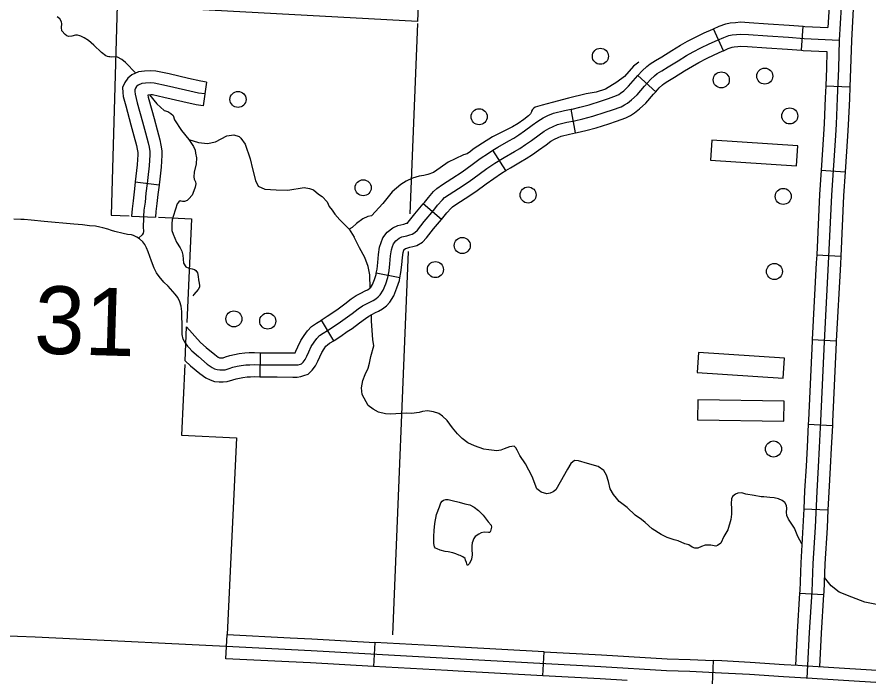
# Model space of a CAD drawing. Extents: x 653372 to 905732, y 627442 to 787275.
# Drawn here: x 693311 to 698620, y 773781 to 777895 of the extents above; entities that cross this region are included whole.
import ezdxf

# ---------------------------------------------------------------- set-up
doc = ezdxf.new("R2010")
doc.units = 0
for name, color, linetype in [('31', 7, 'Continuous'), ('32', 7, 'Continuous'), ('33', 7, 'Continuous'), ('34', 7, 'Continuous'), ('35', 7, 'Continuous'), ('45', 7, 'Continuous'), ('5', 7, 'Continuous'), ('56', 7, 'Continuous'), ('57', 7, 'Continuous'), ('6', 7, 'Continuous')]:
    doc.layers.add(name, color=color, linetype=linetype)

msp = doc.modelspace()

# ---------------------------------------------------------------- linework, layer by layer
at = {"layer": '31'}
for p, q in [((695541.1, 773996.8), (695532.7, 773847.1)), ((696587.2, 773789.1), (696595.4, 773938.9)), ((697649.5, 773883.7), (697642.2, 773733.9))]:
    msp.add_line(p, q, dxfattribs=at)
for points in [[(694613.2, 773895.4), (694620.3, 774045.3), (695013.4, 774025.5)], [(695013.4, 774025.5), (695147.9, 774018.7), (695541.1, 773996.8)], [(701014, 773626.2), (700871.6, 773634.1), (700687.4, 773643.3), (700148.3, 773669.2), (699281.3, 773712.3), (698930.8, 773730.2), (698462, 773758.9), (698233.7, 773773.6), (698228.6, 773773.8), (698087.3, 773782.3), (697875.7, 773796), (697700.5, 773806.1), (697503.3, 773815.7), (697359.2, 773820), (696949.2, 773844.5), (695998.5, 773896.2), (695143.9, 773943.8), (694614.2, 773970.5)], [(696068.2, 773967.6), (696002.6, 773971.1), (695541.1, 773996.8)], [(696595.4, 773938.9), (696068.2, 773967.6)], [(696595.4, 773938.9), (696953.5, 773919.4), (697122.9, 773909.3)], [(697122.9, 773909.3), (697362.6, 773895), (697506.2, 773890.6), (697649.5, 773883.7)], [(695005.9, 773875.7), (694613.2, 773895.4)], [(695532.7, 773847.1), (695139.9, 773869), (695005.9, 773875.7)], [(696060, 773817.8), (695994.4, 773821.4), (695532.7, 773847.1)], [(698177.4, 773852), (698092, 773857.2), (697880.3, 773870.8), (697704.4, 773881), (697649.5, 773883.7)], [(698704.4, 773819.2), (698466.8, 773833.7), (698237.3, 773848.6), (698232, 773848.7), (698177.4, 773852)], [(696587.2, 773789.1), (696060, 773817.8)], [(697114, 773759.5), (696944.9, 773769.6), (696587.2, 773789.1)]]:
    msp.add_lwpolyline(points, dxfattribs=at)
at = {"layer": '32'}
for p, q in [((698199.1, 777688.4), (698209.7, 777838)), ((697714.8, 777685.6), (697651.7, 777821.7)), ((697291.5, 777430.1), (697179.8, 777530.2)), ((698351, 777466.3), (698500.9, 777460.5)), ((696792.4, 777173.4), (696764.1, 777320.7)), ((696357.2, 776938.1), (696277, 777064.9)), ((698322.4, 776941.2), (698472, 776931.2)), ((695957.2, 776634.2), (695843, 776731.4)), ((698294.4, 776412.5), (698444.3, 776405.4)), ((695697.5, 776269.2), (695550.3, 776297.9)), ((695284.9, 775877.4), (695207.7, 776006)), ((694358, 775752.1), (694367.9, 775964.5)), ((698266.5, 775885.7), (698416.3, 775877.7)), ((694825.9, 775653), (694828, 775803)), ((698242.4, 775358.4), (698392.2, 775350.1)), ((698214.3, 774830.5), (698364.2, 774823.5)), ((698187.8, 774304.3), (698337.6, 774295.2))]:
    msp.add_line(p, q, dxfattribs=at)
for points in [[(698493.8, 779045.9), (698478.6, 778678.4), (698468.5, 778464.1), (698452.9, 778065.9), (698435.6, 777752.1), (698430.3, 777575.1), (698423.1, 777389.1), (698416.7, 777228.1), (698412, 777157.9), (698387.1, 776784.8), (698367, 776358.7), (698340.8, 775870.7), (698318.6, 775377.8), (698309.4, 775211), (698303.2, 775092), (698294.4, 774937.5), (698284, 774714.5), (698271, 774489.6), (698263.6, 774314.8), (698248, 774058.3), (698237.7, 773854.9), (698233.7, 773773.6)], [(698373.9, 777995), (698364.8, 777830.5)], [(698523.6, 777986.7), (698510.5, 777748.9), (698505.2, 777572.5), (698500.9, 777460.5)], [(697651.7, 777821.7), (697687.1, 777838), (697727.3, 777852.2), (697756.1, 777858.4), (697787.6, 777862.1), (697820.3, 777864.7), (697874.1, 777861.2), (697992.6, 777853.1), (698123.7, 777844.1), (698209.7, 777838)], [(698209.7, 777838), (698220, 777837.3), (698364.8, 777830.5)], [(695513.3, 776120.9), (695529.8, 776128.2), (695547.5, 776138.9), (695562.3, 776150.2), (695573.4, 776163.1), (695592.3, 776192.3), (695608.6, 776232.3), (695621.6, 776271.9), (695629.6, 776312.7), (695633.8, 776357.6), (695637.9, 776406.2), (695644.1, 776444.2), (695650.4, 776466), (695657, 776482.1), (695671.1, 776500.2), (695692.5, 776516.7), (695710.2, 776524.6), (695740.6, 776532.4), (695758.8, 776537.5), (695773.5, 776541.6), (695791.2, 776551.7), (695806.3, 776567.6), (695847.9, 776621.4), (695907.7, 776691.8), (695932.3, 776722.6), (695961.9, 776756), (695975.8, 776769.6), (696004, 776789.6), (696062.5, 776826.6), (696127.8, 776869.7), (696191.6, 776916.1), (696239.9, 776951.2), (696289.6, 776984.1), (696347.1, 777020.5), (696412.1, 777058), (696445.5, 777076.6), (696480.8, 777100.3), (696517, 777125.6), (696564.7, 777160.2), (696596.9, 777183.9), (696625.6, 777200.1), (696651.3, 777213.4), (696678.5, 777224.8), (696738, 777239.3), (696786.1, 777248.6), (696837.6, 777260), (696898.8, 777277.2), (696976, 777301.4), (697022.6, 777317.4), (697076.6, 777336.6), (697097.7, 777347.2), (697116.1, 777359), (697140.8, 777379.1), (697176.1, 777411.2), (697221.6, 777464.4), (697259.4, 777506.6), (697284.2, 777529.4), (697300.9, 777543), (697329, 777560.2), (697369.1, 777584.3), (697431, 777622.9), (697482.5, 777655.1), (697525.4, 777678), (697573.4, 777703.5), (697623.6, 777729), (697676.6, 777750.5), (697715.3, 777768.5), (697747.7, 777779.9), (697768.4, 777784.3), (697794.9, 777787.4), (697820.8, 777789.5), (697869.1, 777786.3), (697987.5, 777778.3), (698118.5, 777769.3), (698215.6, 777762.4), (698435.6, 777752.1)], [(697179.8, 777530.2), (697205.9, 777559.3), (697235.2, 777586.2), (697257.6, 777604.4), (697290.1, 777624.3), (697329.9, 777648.2), (697391.2, 777686.5), (697445, 777720.1), (697490.1, 777744.2), (697538.8, 777770.1), (697592.5, 777797.4), (697646.7, 777819.3), (697651.8, 777821.7)], [(697291.5, 777430.1), (697312.8, 777453.8), (697333.3, 777472.7), (697344.3, 777481.6), (697367.9, 777496), (697408.3, 777520.3), (697470.7, 777559.3), (697520.1, 777590.1), (697560.7, 777611.8), (697608, 777637), (697654.7, 777660.7), (697706.4, 777681.7), (697714.8, 777685.6)], [(697714.8, 777685.6), (697743.6, 777698.9), (697768.1, 777707.5), (697780.7, 777710.2), (697802.2, 777712.8), (697821.3, 777714.3), (697864.1, 777711.5), (697982.4, 777703.5), (698113.3, 777694.5), (698199.1, 777688.4)], [(698199.1, 777688.4), (698211.2, 777687.6), (698358.4, 777680.7)], [(698358.4, 777680.7), (698355.3, 777577.7), (698351, 777466.3)], [(696764.1, 777320.7), (696770.9, 777322), (696819.3, 777332.7), (696877.5, 777349.1), (696952.6, 777372.6), (696997.8, 777388.2), (697047.1, 777405.7), (697060.5, 777412.4), (697072, 777419.9), (697091.9, 777436), (697122.1, 777463.5), (697165.1, 777513.8), (697179.8, 777530.2)], [(698351, 777466.3), (698348.2, 777392.1), (698341.8, 777232.1), (698337.1, 777162.9), (698322.4, 776941.2)], [(698500.9, 777460.5), (698498.1, 777386.2), (698491.6, 777224.1), (698486.8, 777152.9), (698472, 776931.2)], [(696792.4, 777173.4), (696801.3, 777175.1), (696855.9, 777187.2), (696920.2, 777205.3), (696999.4, 777230.1), (697047.4, 777246.6), (697106.1, 777267.5), (697135, 777282), (697160.1, 777298.2), (697189.7, 777322.2), (697230.1, 777358.9), (697278, 777415), (697291.5, 777430.1)], [(696277, 777064.9), (696308.3, 777084.7), (696375.2, 777123.3), (696406.4, 777140.7), (696438.4, 777162.1), (696473.5, 777186.7), (696520.4, 777220.7), (696556, 777247), (696589.9, 777266.1), (696619.5, 777281.4), (696655.1, 777296.3), (696722, 777312.6), (696764.1, 777320.7)], [(696357.2, 776938.1), (696386, 776956.3), (696449.1, 776992.8), (696484.7, 777012.6), (696523.2, 777038.4), (696560.5, 777064.5), (696609, 777099.6), (696637.8, 777120.9), (696661.2, 777134.1), (696683, 777145.4), (696702, 777153.3), (696754, 777166), (696792.4, 777173.4)], [(695843, 776731.4), (695849.8, 776739.5), (695874.9, 776770.9), (695907.6, 776807.7), (695927.6, 776827.3), (695962.2, 776851.9), (696021.8, 776889.6), (696085.1, 776931.4), (696147.5, 776976.8), (696197.2, 777012.8), (696248.8, 777047.1), (696277, 777064.9)], [(695957.2, 776634.2), (695965.6, 776644.1), (695989.7, 776674.2), (696016.3, 776704.3), (696024.1, 776711.9), (696045.8, 776727.3), (696103.1, 776763.6), (696170.6, 776808), (696235.8, 776855.5), (696282.7, 776889.6), (696330.4, 776921.2), (696357.2, 776938.1)], [(698322.4, 776941.2), (698312.2, 776789), (698294.4, 776412.5)], [(698472, 776931.2), (698462, 776780.5), (698444.3, 776405.4)], [(695550.3, 776297.9), (695555.3, 776323.4), (695559.1, 776364.2), (695563.4, 776415.4), (695570.8, 776460.7), (695579.5, 776490.8), (695591.6, 776520), (695617.7, 776553.8), (695653.9, 776581.5), (695685.3, 776595.6), (695721.1, 776604.9), (695738.7, 776609.8), (695744.5, 776611.4), (695744.5, 776611.4), (695749.3, 776616.5), (695789.6, 776668.7), (695843, 776731.4)], [(695697.5, 776269.2), (695703.9, 776302), (695708.5, 776351), (695712.4, 776397), (695717.4, 776427.7), (695721.2, 776441.1), (695722.5, 776444.1), (695724.4, 776446.6), (695731.2, 776451.8), (695735.1, 776453.5), (695760.1, 776460), (695778.8, 776465.2), (695802.5, 776471.8), (695838, 776492.1), (695863.3, 776518.7), (695906.2, 776574.2), (695957.2, 776634.2)], [(698294.4, 776412.5), (698292.1, 776362.5), (698266.5, 775885.7)], [(698444.3, 776405.4), (698441.9, 776355), (698416.3, 775877.7)], [(695206.7, 776005.5), (695244.8, 776031), (695284.8, 776058.4), (695313.3, 776077.4), (695354.7, 776108.1), (695393.4, 776137.9), (695425.1, 776159.9), (695454.2, 776175), (695481, 776188.6), (695495, 776194.8), (695505.3, 776201), (695510.6, 776205.1), (695513.1, 776208), (695525.5, 776227.2), (695538.2, 776258.3), (695548.9, 776290.9), (695550.3, 776297.9)], [(695284.8, 775877.4), (695287.1, 775878.8), (695328.9, 775906.8), (695368.8, 775934.1), (695399.7, 775954.7), (695445.2, 775988.4), (695482, 776016.8), (695502.8, 776031.2), (695522.6, 776041.5), (695545.6, 776053.1), (695564.6, 776061.7), (695589.6, 776076.8), (695614.1, 776095.3), (695633.6, 776118.2), (695659, 776157.5), (695679.1, 776206.4), (695694.4, 776252.9), (695697.5, 776269.2)], [(694362.9, 775858.1), (694373.4, 775844.5), (694383.7, 775833.6), (694401, 775814), (694441.9, 775778.7), (694496.4, 775732.3), (694526.6, 775710.2), (694541.5, 775703), (694558.1, 775698), (694574.8, 775695.9), (694592.2, 775696.4), (694608.4, 775697.1), (694632.7, 775704.7), (694656.4, 775712.4), (694682.3, 775718.3), (694707, 775723.2), (694737.9, 775726.7), (694762, 775728.3), (694791.6, 775729), (694826.3, 775728), (694932.4, 775726.5), (695030.5, 775726.3), (695051.7, 775726.3), (695064.1, 775728.1), (695077.6, 775731.6), (695084.9, 775734.2), (695094.7, 775743.4), (695107.5, 775760.4), (695117.7, 775781.3), (695129.1, 775807.8), (695145.2, 775842), (695162.8, 775868.3), (695178.5, 775890.8), (695196.4, 775909.3), (695218.1, 775924.8), (695246.9, 775942.1), (695286.9, 775968.9), (695326.8, 775996.2), (695356.5, 776016), (695399.9, 776048.3), (695437.7, 776077.3), (695464, 776095.5), (695488.4, 776108.2), (695513.3, 776120.9)], [(694828, 775803), (694933, 775801.5), (695030.7, 775801.3), (695044, 775801.3), (695049.4, 775812.5), (695060.7, 775838.7), (695079.7, 775879), (695100.9, 775910.7), (695120.5, 775938.7), (695147.2, 775966.3), (695176.9, 775987.6), (695207.7, 776006)], [(694367.9, 775964.5), (694453.8, 775867.5), (694490.7, 775835.6), (694542.9, 775791.2), (694565.4, 775774.7), (694568.7, 775773.2), (694573.8, 775771.6), (694578.4, 775771), (694589.4, 775771.4), (694595.4, 775771.6), (694609.9, 775776.2), (694636.4, 775784.8), (694666.7, 775791.7), (694695.5, 775797.4), (694731.3, 775801.5), (694758.6, 775803.2), (694791.8, 775804.1), (694827.9, 775803), (694828, 775803)], [(694825.9, 775653), (694931.8, 775651.5), (695030.3, 775651.3), (695057.2, 775651.2), (695079.1, 775654.6), (695099.5, 775659.8), (695124.8, 775668.7), (695150.7, 775693.2), (695171.8, 775721.1), (695185.9, 775750.1), (695197.5, 775777), (695210.7, 775805), (695224.7, 775826), (695236.5, 775842.9), (695245.6, 775852.2), (695259.4, 775862.1), (695284.9, 775877.4)], [(698266.5, 775885.7), (698265.9, 775874.4), (698243.7, 775381.5), (698242.4, 775358.4)], [(698416.3, 775877.7), (698415.7, 775867), (698393.5, 775374), (698392.2, 775350.1)], [(694358, 775752.1), (694393, 775721.8), (694449.9, 775673.4), (694487.9, 775645.6), (694514.3, 775632.8), (694542.4, 775624.4), (694571.3, 775620.7), (694594.9, 775621.5), (694621.4, 775622.5), (694655.5, 775633.3), (694676.4, 775640), (694697.9, 775645), (694718.5, 775649), (694744.5, 775652), (694765.3, 775653.3), (694791.5, 775654), (694824.6, 775653), (694825.9, 775653)], [(698242.4, 775358.4), (698234.5, 775215), (698228.3, 775096.1), (698219.5, 774941.3), (698214.3, 774830.5)], [(698392.2, 775350.1), (698384.3, 775207), (698378.1, 775087.9), (698369.3, 774933.6), (698364.2, 774823.5)], [(698214.3, 774830.5), (698209.1, 774718.4), (698196.1, 774493.4), (698188.7, 774318.6), (698187.8, 774304.3)], [(698364.2, 774823.5), (698358.9, 774710.6), (698345.9, 774485.9), (698338.5, 774310.9), (698337.6, 774295.2)], [(698187.8, 774304.3), (698173.2, 774062.5), (698162.5, 773852.6)], [(698337.6, 774295.2), (698322.9, 774054.2), (698312.3, 773843.7)]]:
    msp.add_lwpolyline(points, dxfattribs=at)
at = {"layer": '33'}
msp.add_lwpolyline([(694614.2, 773970.5), (694233.4, 773989.4), (693983.5, 774002.5), (693423.7, 774028.6), (692982.8, 774045.6), (692965.1, 774045.2), (692667.6, 774056.9), (692428.2, 774064.8), (692378.2, 774067.5), (691940.2, 774090.1), (691859.4, 774094.8), (691393, 774119.4), (691053.9, 774134.6), (690550.6, 774158.3), (690294.9, 774171.4), (689795.4, 774198.8)], dxfattribs=at)
at = {"layer": '34'}
for points in [[(694362.9, 775858.1), (694347.3, 775887.3), (694339.8, 775916.1), (694340.8, 775949.6), (694337.4, 776059.9), (694333.4, 776093.6), (694325.8, 776119.5), (694312.6, 776147.9), (694297, 776168.5), (694252.1, 776217.9), (694226.6, 776243), (694196.3, 776277.5), (694179.7, 776301.4), (694166.6, 776329.2), (694150.1, 776374.5), (694128.9, 776432.7), (694118.4, 776456), (694106.8, 776477.6), (694095, 776494.1), (694074.8, 776513.2), (694058.4, 776523.2), (694036.9, 776533.3), (694023.6, 776537.1), (693999.6, 776540), (693972.4, 776546.5), (693920.8, 776559.2), (693899.2, 776564.9), (693877, 776572.2), (693845.5, 776582.1), (693827.7, 776585.5), (693801, 776590.7), (693763.2, 776594.7), (693719.2, 776599.4), (693664.5, 776603.8), (693481.1, 776620.8), (693398.6, 776628.8), (693355.7, 776632.9), (693333.9, 776633), (693291, 776636)], [(694098.6, 776651.5), (694098.3, 776639.8), (694097.9, 776587.6), (694098.9, 776559), (694098, 776548.5), (694091.5, 776537.5), (694069.1, 776516.5)]]:
    msp.add_lwpolyline(points, dxfattribs=at)
at = {"layer": '35'}
for points in [[(694051.9, 777545.7), (693987.7, 777611.1), (693964.6, 777629.8), (693937.1, 777644.3), (693928.5, 777647.1), (693899.7, 777646.2), (693890.5, 777646.8), (693882.4, 777646.4), (693874.5, 777649.3), (693865.4, 777653.3), (693838, 777674.6), (693789.1, 777719.6), (693757.1, 777749.7), (693729.4, 777765.6), (693709.5, 777775.3), (693702.8, 777779.2), (693688.3, 777782.4), (693676.6, 777783.3), (693651.8, 777776.4), (693631.8, 777773.9), (693621.4, 777777.3), (693611.7, 777786.9), (693589.4, 777808.7), (693587.6, 777829.3), (693591.4, 777852.8), (693588.2, 777866.4), (693578.8, 777884.1), (693561.2, 777896.4)], [(697186.2, 777613.1), (697152.6, 777590.1), (697097.7, 777524.8), (697049.4, 777489), (696977.8, 777446.4), (696919.3, 777427.5), (696857, 777416.9), (696747.7, 777388.8), (696645.2, 777362.1), (696583.9, 777346.2), (696540.4, 777332.6), (696532.8, 777327), (696523.5, 777318.2), (696518.2, 777308.4), (696516.4, 777305.2), (696511.9, 777292.9), (696498.3, 777280.1), (696470.3, 777256.9), (696434.8, 777231.5), (696398.6, 777211), (696337.3, 777179), (696275.1, 777148.5), (696211.1, 777109.9), (696154.5, 777071.9), (696137.1, 777057.5), (696116.8, 777043.2), (696092.6, 777036.5), (696040.6, 777010.7), (695997.8, 776991.3), (695947.9, 776956.4), (695905.6, 776926.2), (695871.3, 776914), (695846.3, 776906.6), (695816.4, 776903.3), (695776.5, 776891.6), (695736.1, 776872.3), (695702.9, 776851.6), (695649.6, 776806.1), (695591.8, 776732.9), (695519.5, 776656.8)], [(694135.9, 777410.8), (694182.8, 777354.2), (694204.7, 777334.2), (694228, 777312.4), (694251.5, 777306), (694269.2, 777294.2), (694284.6, 777282.5), (694292.8, 777255.2), (694337, 777187.3), (694381.6, 777133), (694410.6, 777088.2), (694421.2, 777065.3), (694424, 777046.1), (694429.9, 777017.7), (694426.6, 776980.6), (694416, 776929.1), (694412.8, 776898.7), (694415.8, 776884), (694424.3, 776867.9), (694426.2, 776855.5), (694421, 776834.2), (694412.5, 776812.2), (694402.1, 776784.9), (694382.3, 776762.4), (694370.7, 776752.1), (694354.7, 776746.3), (694343.4, 776746.1), (694335, 776747.5), (694327.8, 776748.8), (694318.6, 776743.5), (694309.7, 776730.8), (694299.2, 776698.4), (694283.7, 776652.1), (694278.6, 776632), (694275.6, 776608.4), (694275.6, 776587.5), (694276.6, 776565.5), (694284.4, 776542.7), (694304.3, 776492.9), (694327.4, 776457.2), (694339.2, 776434.9), (694344.1, 776411.6), (694345.6, 776385.1), (694348.8, 776361.3), (694363.3, 776338.9), (694381.1, 776329.9), (694401.8, 776325.9), (694417.5, 776322), (694426.3, 776316.1), (694435.5, 776301.2), (694440.4, 776278), (694443.1, 776257), (694447, 776236.4), (694447.7, 776221.8), (694447.4, 776211.1), (694440.2, 776196.6), (694413.4, 776166.4), (694407.7, 776156.9)], [(694381.6, 777133), (694442.8, 777112.7), (694498.5, 777107.3), (694547.3, 777118.3), (694618, 777155.9), (694661.6, 777162), (694694.8, 777151.1), (694706.9, 777139.6), (694733.1, 777102.8), (694763.9, 777011.1), (694779.4, 776948.6), (694797.1, 776877.2), (694814.6, 776840.7), (694856.3, 776822), (694927, 776817.4), (694999, 776816.5), (695100.1, 776833.3), (695134.2, 776826.8), (695158.8, 776817.4), (695190.3, 776791.6), (695212.2, 776776.1), (695243.5, 776744.1), (695256.3, 776715.1), (695275.5, 776690.9), (695292.1, 776666.8), (695322.1, 776631.1), (695381.2, 776573.5), (695412.6, 776522.8)], [(695519.5, 776656.8), (695497.9, 776651), (695466.9, 776637.9), (695427.1, 776608.5), (695399.8, 776582.8), (695381.2, 776573.5)], [(695512.3, 776202.6), (695510.7, 776287.8), (695498.7, 776341.2), (695477.9, 776397.2), (695445.1, 776456), (695412.6, 776522.8)], [(696996.1, 774999.8), (696983.7, 775039.8), (696967.7, 775067.6), (696933.1, 775092.7), (696867.1, 775113.2), (696809.7, 775128.6), (696785.6, 775130.1), (696762.6, 775113.1), (696740.7, 775076.8), (696694.9, 774996.3), (696669.3, 774947.2), (696651.3, 774935.7), (696632.6, 774927.4), (696612.4, 774924), (696578.1, 774933.1), (696567.1, 774941.4), (696551.5, 774954.8), (696521.1, 775030.4), (696479.3, 775109.6), (696444.8, 775162.8), (696428.1, 775196.3), (696419.7, 775210.2), (696409.6, 775219.3), (696380.6, 775217), (696346.4, 775203.6), (696326.9, 775195.3), (696300.3, 775192.1), (696251.5, 775196.8), (696221.1, 775202.5), (696162.3, 775222.7), (696120.3, 775241.7), (696084.4, 775267.6), (696055.6, 775297.4), (696024.6, 775334.5), (695991.5, 775380.5), (695962.6, 775407.9), (695940.6, 775424.6), (695906.4, 775435.3), (695868.7, 775439.6), (695838.9, 775436.5), (695816.3, 775429.9), (695769.5, 775424.1), (695740.6, 775425), (695702, 775422.9), (695641.3, 775420.6), (695608.4, 775421.6), (695564.5, 775431.8), (695531.4, 775450.4), (695499.9, 775473.1), (695461.8, 775542), (695458.2, 775583.1), (695465.2, 775629.5), (695481.6, 775666.8), (695499.7, 775706.4), (695507.8, 775736.7), (695516.3, 775779.8), (695534.4, 775845.1), (695527.5, 775884.5), (695524.2, 775940.5), (695520.4, 776002.1), (695520.5, 776040.4)], [(697270.2, 774705), (697226.3, 774744.3), (697203.8, 774762.7), (697164, 774790.4), (697114.1, 774837), (697064.3, 774875.7), (697046.8, 774895.7), (697027.5, 774919.6), (697007.7, 774954.4), (696996.1, 774999.8)], [(698202.9, 774611.3), (698177.9, 774657.4), (698156.4, 774708.4), (698118.4, 774766.2), (698108.5, 774788.6), (698105.5, 774808.1), (698108, 774831.1), (698106.8, 774850.6), (698096.7, 774868.5), (698080.3, 774882.3), (698056.8, 774891.8), (698030.4, 774897.9), (698002.2, 774899.7), (697966.1, 774904.3), (697949.3, 774904.8), (697905.3, 774912.3), (697853.4, 774920.9), (697828.9, 774928.8), (697803.7, 774927.2), (697788, 774921.1), (697769.9, 774905.8), (697764.1, 774891.8), (697762.5, 774863), (697763.2, 774830.8), (697763.1, 774795.8), (697760.3, 774762.8), (697741.2, 774698.7), (697715.1, 774656.2), (697696.6, 774616.1), (697676.3, 774600.3), (697666.5, 774597.5), (697634.8, 774602.1), (697615.4, 774602.2), (697598.6, 774602.3), (697576.3, 774595), (697553.9, 774585), (697535.3, 774584.7), (697518.7, 774591.4), (697497.9, 774604.4), (697472.9, 774611.4), (697430.6, 774629.9), (697406.9, 774635.4), (697362.3, 774651.8), (697324.8, 774668.9), (697270.2, 774705)], [(696026.3, 774554.9), (695998.6, 774561.7), (695979.5, 774564.3), (695947.9, 774572.5), (695929.6, 774581), (695919.1, 774585.3), (695912.7, 774592.8), (695909.4, 774612.8), (695908.7, 774656.5), (695911.1, 774693.6), (695915.8, 774738.5), (695926.1, 774793.9), (695944.1, 774841.8), (695952.1, 774866.1), (695961.1, 774877.7), (695967.9, 774883.5), (695982.6, 774888.3), (695997.8, 774888.6), (696022.8, 774882.5), (696066.3, 774871.9), (696102.4, 774860.2), (696132.7, 774854)], [(696132.7, 774854), (696160.1, 774839.9), (696187.3, 774819.9), (696216.2, 774789.2), (696247.5, 774749.1), (696266.7, 774728.7), (696267.7, 774715.4), (696261.6, 774689.7), (696256.7, 774682.6), (696248.8, 774681.5), (696222.3, 774683.6), (696204.3, 774680.8), (696188.2, 774672), (696167.2, 774656.7), (696158.2, 774645.1), (696148.1, 774618.2), (696145.6, 774599), (696145.6, 774577.8), (696146.5, 774542), (696143.7, 774516.2), (696131, 774488.8), (696121.4, 774478.4), (696118.1, 774477.9), (696116.8, 774479.3), (696115, 774486.6), (696112.6, 774495.3), (696107, 774508.7), (696103.4, 774520.1), (696089.8, 774529.8), (696072.8, 774538.9), (696063.6, 774540.5), (696046.6, 774548.3), (696026.3, 774554.9)], [(698688.8, 774229.2), (698594.4, 774248.7), (698514, 774278.5), (698433.6, 774311), (698384.4, 774350.5), (698342.3, 774401.9)]]:
    msp.add_lwpolyline(points, dxfattribs=at)
at = {"layer": '45'}
for p, q in [((694491.6, 777489.9), (694470.6, 777341.4)), ((694047.5, 776869.1), (694196.3, 776850))]:
    msp.add_line(p, q, dxfattribs=at)
for points in [[(694491.6, 777489.9), (694455.9, 777495), (694379, 777512.8), (694259.4, 777540.7), (694176.1, 777558.7), (694145.3, 777560.5), (694105.1, 777558), (694069, 777553.2), (694026.2, 777534.5), (694001.4, 777514.5), (693982.6, 777488.1), (693969.4, 777455.7), (693970.1, 777425.3), (693973.1, 777399.8), (693984.4, 777357.1)], [(694481.1, 777415.7), (694442.1, 777421.2), (694362, 777439.8), (694243, 777467.6), (694165.9, 777484.2), (694145.4, 777485.4), (694112.4, 777483.3), (694089.4, 777480.2), (694065.4, 777469.8), (694056.5, 777462.6), (694048.8, 777451.7), (694044.7, 777441.8), (694045, 777430.6), (694047, 777413.8), (694060.9, 777361.2), (694093.4, 777242.8), (694111.8, 777173.8), (694128.6, 777111.8), (694134, 777084.9), (694138.1, 777056.2), (694138.1, 777035.1), (694137.1, 777002.2), (694134.2, 776967.5), (694126.4, 776894.4), (694121.5, 776856.7), (694114.8, 776798.3), (694108.8, 776742), (694102.3, 776690.6), (694098.6, 776651.5)], [(694470.6, 777341.4), (694428.4, 777347.4), (694345, 777366.7), (694226.5, 777394.4), (694155.6, 777409.6), (694145.5, 777410.3), (694125.9, 777409), (694129.4, 777395.6)], [(693984.4, 777357.1), (693988.5, 777341.7), (694021, 777223.3), (694039.4, 777154.3), (694055.5, 777094.6), (694060, 777072.2), (694063.1, 777050.9), (694063.1, 777036.2), (694062.2, 777006.5), (694059.5, 776974.6), (694051.9, 776903.2), (694047.5, 776869.1)], [(694129.4, 777395.6), (694133.4, 777380.7), (694165.8, 777262.4), (694184.3, 777193.2), (694201.6, 777129), (694207.9, 777097.6), (694213.1, 777061.5), (694213.1, 777033.9), (694212, 776997.9), (694208.9, 776960.4), (694200.9, 776885.7), (694196.3, 776850)], [(694047.5, 776869.1), (694047.1, 776865.8), (694040.3, 776806.6), (694034.3, 776750.7), (694027.7, 776698.9), (694023.6, 776655), (694173.6, 776648)], [(694196.3, 776850), (694196, 776847.6), (694189.4, 776790), (694183.3, 776733.3), (694176.8, 776682.4), (694173.6, 776648)]]:
    msp.add_lwpolyline(points, dxfattribs=at)
at = {"layer": '5'}
for points in [[(695807.2, 777855.9), (695758.8, 776668.9)], [(695749.3, 776433.5), (695651.9, 774043.4)]]:
    msp.add_lwpolyline(points, dxfattribs=at)
at = {"layer": '56'}
for centre in [(696946.5, 777650.7), (697971, 777527.4), (697700.1, 777503.3), (694688.3, 777381.9), (696191, 777274.2), (698126.7, 777278.8), (695468.4, 776831), (696496.2, 776786.1), (698085.8, 776777.4), (696085.9, 776471.3), (695918.3, 776320.8), (698031, 776309.2), (694662.5, 776013.6), (694873.4, 776000.2), (698025.5, 775202.5)]:
    msp.add_circle(centre, 50, dxfattribs=at)
at = {"layer": '57'}
for p, q in [((697640.7, 777127.3), (697632.7, 777002.6)), ((698177.1, 777092.6), (697640.7, 777127.3)), ((698169, 776967.9), (698177.1, 777092.6)), ((697632.7, 777002.6), (698169, 776967.9)), ((697558.2, 775803.9), (697550.2, 775679.1)), ((698094.6, 775769.4), (697558.2, 775803.9)), ((698086.6, 775644.7), (698094.6, 775769.4)), ((697550.2, 775679.1), (698086.6, 775644.7)), ((697553.7, 775510), (697551.5, 775385)), ((698091.2, 775500.4), (697553.7, 775510)), ((698088.9, 775375.4), (698091.2, 775500.4)), ((697551.5, 775385), (698088.9, 775375.4))]:
    msp.add_line(p, q, dxfattribs=at)
at = {"layer": '6'}
for points in [[(698452.8, 779032.4), (695860.9, 779173.3), (695807.6, 777866.7), (693936.2, 777970.3), (693896.9, 776661), (694010.6, 776655.6)], [(694193.7, 776647), (694399.5, 776637.4), (694369.2, 775990.6)], [(694356.9, 775728.9), (694336.2, 775288.1), (694677.9, 775272.1), (694620.3, 774045.3)]]:
    msp.add_lwpolyline(points, dxfattribs=at)

# ---------------------------------------------------------------- texts
at = {"layer": '5'}
msp.add_text('31', height=422.4, rotation=358.28, dxfattribs=at).set_placement((693413.7, 775799.1))

doc.saveas('drawing.dxf')
